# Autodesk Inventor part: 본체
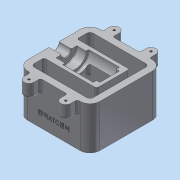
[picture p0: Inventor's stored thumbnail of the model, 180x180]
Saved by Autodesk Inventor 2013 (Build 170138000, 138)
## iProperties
Created: 2018-01
Part Number: 본체
Material: 알루미늄 6061
Document SubType Name: Modeling
Designer: dgall
Density: 2.71 g/cm^3
Mass: 998.129 g
Surface Area: 836.577 cm^2
Volume: 368.313 cm^3
Author: dgall
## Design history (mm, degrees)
sketch "스케치1"
  geometry: L1 (0, 0)-(110, 0); L2 (110, 0)-(110, 110); L3 (110, 110)-(0, 110); L4 (0, 110)-(0, 0)
  constraints: 8 end point, 2 parallel, 1 horizontal, 1 perpendicular
  dimensions: "d0" = 110 distance between parallel lines of L2 L4; "d2" = 110 distance between parallel lines of L1 L3
extrude "돌출1" new body sketch "스케치1" distance "d3" = 65; taper "d4" = 0 deg
sketch "스케치2"
  geometry: L1 (110, 110)-(0, 110) reference; L2 (0, 110)-(0, 0) reference; L3 (19.5, 120)-(19.5, 110); L4 (34.5, 120)-(34.5, 110); A1 r 7.5 centre (27, 120) between (34.5, 120) and (19.5, 120)
  constraints: 4 end point, 2 point on circle, 2 point on line, 2 tangent, 1 centre point, 1 parallel, 1 perpendicular
  dimensions: "d6" = 7.5 radius of A1; "d7" = 10 distance from line of A1.centre L1; "d8" = 27 distance from line of A1.centre L2
extrude "돌출2" join sketch "스케치2" distance "d9" = 20; taper "d10" = 0 deg
hole "구멍1" diameter "d13" = 3.242; stored, may be unused: countersink angle "d17" = 90 deg, drill point angle "d19" = 118 deg; dims "d11" = 10, "d12" = 10, "d14" = 9, "d15" = 4, "d16" = 2, "d18" = 11
node "작업 평면1"
fillet "모깎기1" dims "d23" = 15
sketch "스케치3"
  geometry: L1 (0, 0)-(85, 0); L2 (0, 0)-(0, -7.5); L3 (0, -7.5)-(19, -7.5); L4 (19, -7.5)-(19, -16); L5 (19, -16)-(33, -16); L6 (33, -16)-(33, -20); L7 (33, -20)-(80, -20); L8 (80, -20)-(80, -15); L9 (80, -15)-(85, -15); L10 (85, -15)-(85, 0)
  constraints: 20 end point, 7 parallel, 2 perpendicular, 1 horizontal
  dimensions: "d25" = 15 diameter of L3 L1; "d26" = 32 diameter of L5 L1; "d27" = 40 diameter of L7 L1; "d28" = 30 diameter of L9 L1; "d29" = 19 distance between parallel lines of L4 L2; "d30" = 14 distance between parallel lines of L6 L4; "d31" = 47 distance between parallel lines of L8 L6; "d32" = 5 distance between parallel lines of L10 L8
revolve "회전1" sketch "스케치3" stored, may be unused: angle "d33" = 90 deg
sketch "스케치4"
  geometry: L1 (34.5, 0)-(75.5, 0) reference; L2 (110, 15)-(110, 95) reference; L3 (75.5, 110)-(34.5, 110) reference; L4 (0, 95)-(0, 62.5) reference; L5 (0, 47.5)-(0, 62.5) reference; L6 (90, 80)-(90, 30); L7 (90, 30)-(10, 30); L8 (10, 30)-(10, 10); L9 (10, 10)-(100, 10); L10 (100, 10)-(100, 100); L11 (100, 100)-(10, 100); L12 (10, 100)-(10, 80); L13 (10, 80)-(90, 80); 4 further points
  constraints: 16 end point, 4 parallel, 3 midpoint, 2 perpendicular, 1 collinear, 1 horizontal alignment, 1 vertical alignment
  dimensions: "d36" = 20 distance between parallel lines of L2 L6; "d38" = 30 distance between parallel lines of L13 L3; "d39" = 10 distance between parallel lines of L9 L1; "d41" = 10 distance between parallel lines of L3 L11; "d42" = 10 distance between parallel lines of L12 L4; "d43" = 10 distance between parallel lines of L2 L10
extrude "돌출3" cut sketch "스케치4" stored distance "d44" = 20; taper "d45" = 0 deg
fillet "모깎기2" dims "d46" = 5
sketch "스케치5"
  geometry: L1 (100, -65)-(100, 0) reference; L2 (100, 0)-(110, 0) reference; L3 (110, 0)-(110, -65) reference; L4 (110, -65)-(100, -65) reference; L5 (0, -7.5)-(19, -7.5) reference; L6 (19, -7.5)-(19, -16) reference; L7 (19, -16)-(33, -16) reference; L8 (33, -16)-(33, -20) reference; L9 (33, -20)-(80, -20) reference; L10 (80, -20)-(80, -15) reference; L11 (80, -15)-(85, -15) reference; L12 (85, -15)-(85, 0) reference; L13 (85, 0)-(90, 0) reference; L14 (90, 0)-(90, -65) reference; L15 (90, -65)-(0, -65) reference; L16 (0, -65)-(0, -7.5) reference; L17 (10, -65)-(10, -56.436); L18 (10, -56.436)-(90, -35); L19 (0, -35.939)-(38, -25.757); L20 (38, -25.757)-(38, -20); L21 (75, -20)-(75, -33.843); L22 (75, -33.843)-(0, -53.939); 1 further point
  constraints: 12 end point, 6 point on line, 3 parallel, 1 perpendicular
  dimensions: "d47" = 105 deg angle of L18 L17; "d50" = 30 distance from line of L18.end L15; "d51" = 10 distance between parallel lines of L17 L16; "d64" = 5 distance between parallel lines of L22 L18; "d65" = 5 distance between parallel lines of L10 L21; "d66" = 37 distance between parallel lines of L20 L21; "d67" = 18 distance of L19.start L22.end
  node "절단 모서리 투영1"
extrude "돌출4" cut sketch "스케치5" stored distance "d55" = 50; taper "d56" = 0 deg
extrude "돌출6" cut sketch "스케치5" stored distance "d68" = 30; taper "d69" = 0 deg
sketch "스케치7"
  geometry: L1 (100, 95)-(100, 15) reference; L2 (80, 40)-(80, 35) reference; L3 (33, 35)-(33, 39) reference; L4 (38, 70)-(75, 70); L5 (75, 70)-(75, 40); L6 (75, 40)-(38, 40); L7 (38, 40)-(38, 70); 3 further points
  constraints: 8 end point, 2 midpoint, 2 parallel, 1 horizontal, 1 horizontal alignment, 1 perpendicular
  dimensions: "d70" = 5 distance between parallel lines of L7 L3; "d71" = 5 distance between parallel lines of L2 L5; "d72" = 30 distance between parallel lines of L4 L6
extrude "돌출7" cut sketch "스케치7" stored distance "d73" = 80; taper "d74" = 0 deg
chamfer "모따기1" distance "d75" = 1; stored, may be unused: second distance "d76" = 2, angle "d77" = 45 deg
fillet "모깎기3" dims "d78" = 1
sketch "스케치8" dims "d0" = 110, "d2" = 110
  geometry: L1 (60.5, -65)-(-19.5, -65) reference; L2 (-34.5, 0)-(-34.5, -65) reference; 1 further point
  constraints: 1 other
  dimensions: "d79" = 55 distance from line of point (20.5, -45) L2; "d80" = 20 distance from line of point (20.5, -45) L1
feature "엠보싱1" sketch "스케치8" dims "d0" = 110, "d2" = 110, "d81" = 0.5, "d82" = 0
fillet "모깎기4" dims "d83" = 3
fillet "모깎기5" dims "d84" = 3
fillet "모깎기6" dims "d85" = 3
fillet "모깎기7" dims "d86" = 3
fillet "모깎기8" dims "d87" = 3
fillet "모깎기9" dims "d88" = 3
fillet "모깎기10" dims "d89" = 3
node "솔리드1"
pattern_linear "직사각형 패턴1" dims "d22" = 56
mirror "대칭1"
